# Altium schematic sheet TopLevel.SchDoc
size A
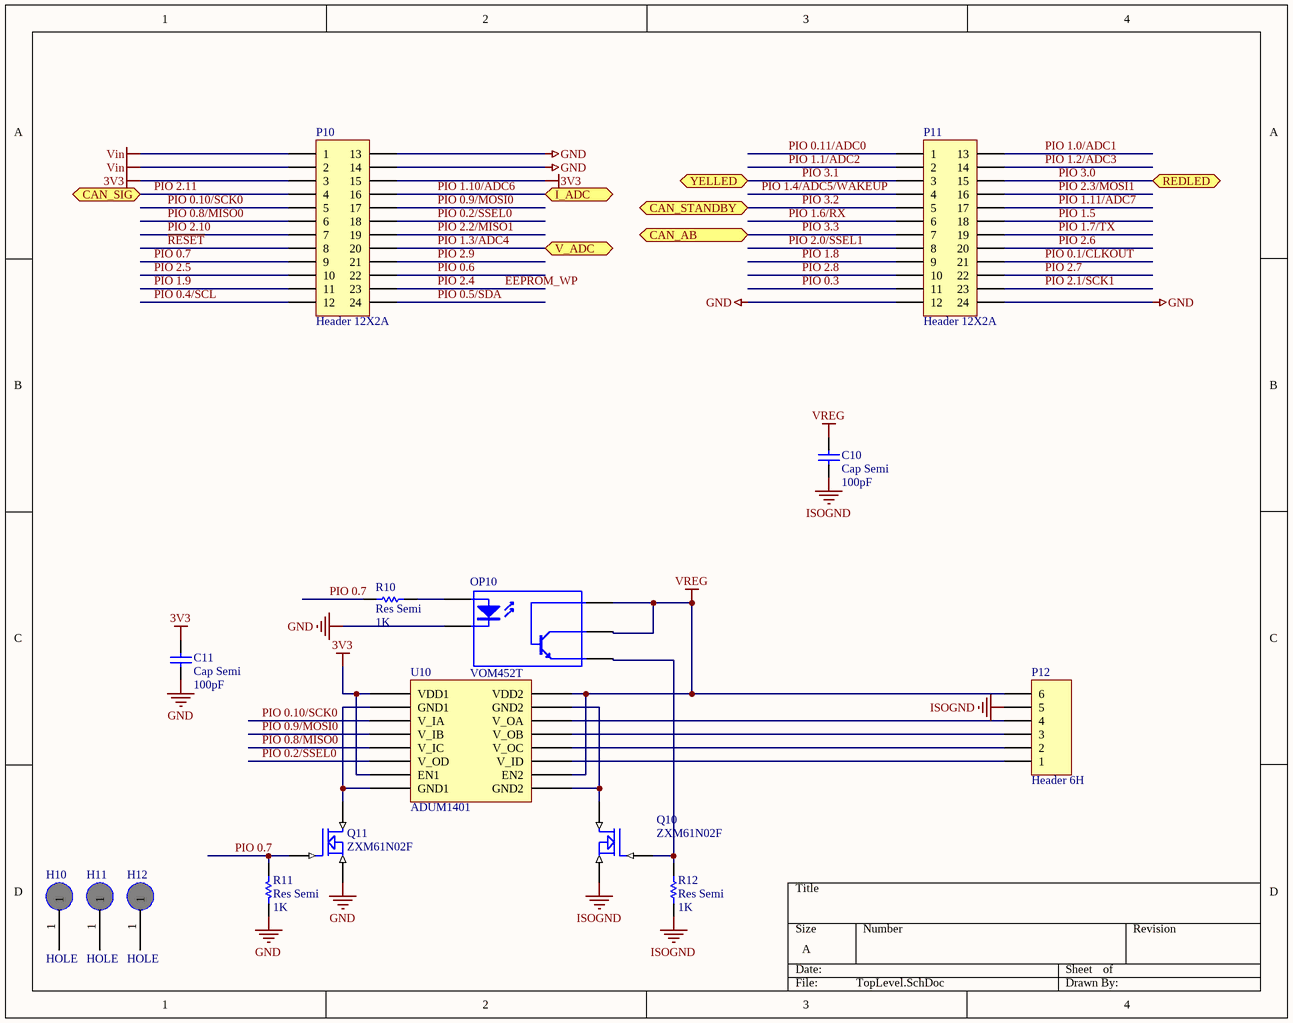
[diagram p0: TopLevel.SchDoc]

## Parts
C10  Cap Semi  value 100pF  [1608[0603]]
C11  Cap Semi  value 100pF  [1608[0603]]
H10  HOLE  [M2.5]
H11  HOLE  [M2.5]
H12  HOLE  [M2.5]
OP10  VOM452T  [VOM452T]
P10  Header 12X2A  [HDR2X12_CEN]
P11  Header 12X2A  [HDR2X12_CEN]
P12  Header 6H  [HDR1X6H]
Q10  ZXM61N02F  [SOT23-3]
Q11  ZXM61N02F  [SOT23-3]
R10  Res Semi  value 1K  [0603]
R11  Res Semi  value 1K  [0603]
R12  Res Semi  value 1K  [0603]
U10  ADUM1401  [SOIC_16_wide]

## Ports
CAN_AB, CAN_SIG, CAN_STANDBY, I_ADC, REDLED (bidir), V_ADC, YELLED (bidir)

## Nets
3V3: C11.2 P10.3 P10.15 U10.1(VDD1) U10.7(EN1)
GND: C11.1 OP10.3(K) P10.13 P10.14 P11.12 P11.24 Q11.2(S) R11.1
ISOGND: C10.1 P12.5 Q10.2(S) R12.1
Vin: P10.1 P10.2
VREG: C10.2 OP10.5(C) OP10.6(C) P12.6 U10.10(EN2) U10.16(VDD2)
EEPROM_WP: P10.23  [also labelled PIO 2.4]
PIO 0.1/CLKOUT: P11.21
PIO 0.2/SSEL0: P10.18 U10.6(V_OD)
PIO 0.3: P11.11
PIO 0.4/SCL: P10.12
PIO 0.5/SDA: P10.24
PIO 0.6: P10.22
PIO 0.7: P10.9 Q11.1(G) R10.2 R11.2
PIO 0.8/MISO0: P10.6 U10.5(V_IC)
PIO 0.9/MOSI0: P10.17 U10.4(V_IB)
PIO 0.10/SCK0: P10.5 U10.3(V_IA)
PIO 0.11/ADC0: P11.1
PIO 1.0/ADC1: P11.13
PIO 1.1/ADC2: P11.2
PIO 1.2/ADC3: P11.14
PIO 1.3/ADC4: P10.20 ; port V_ADC
PIO 1.4/ADC5/WAKEUP: P11.4
PIO 1.5: P11.18
PIO 1.6/RX: P11.6
PIO 1.7/TX: P11.19
PIO 1.8: P11.9
PIO 1.9: P10.11
PIO 1.10/ADC6: P10.16 ; port I_ADC
PIO 1.11/ADC7: P11.17
PIO 2.0/SSEL1: P11.8
PIO 2.1/SCK1: P11.23
PIO 2.2/MISO1: P10.19
PIO 2.3/MOSI1: P11.16
PIO 2.5: P10.10
PIO 2.6: P11.20
PIO 2.7: P11.22
PIO 2.8: P11.10
PIO 2.9: P10.21
PIO 2.10: P10.7
PIO 2.11: P10.4 ; port CAN_SIG
PIO 3.0: P11.15 ; port REDLED
PIO 3.1: P11.3 ; port YELLED
PIO 3.2: P11.5 ; port CAN_STANDBY
PIO 3.3: P11.7 ; port CAN_AB
~{RESET}: P10.8
NetOP10_1: OP10.1(A) R10.1
NetOP10_4: OP10.4(E) Q10.1(G) R12.2
NetP12_1: P12.1 U10.11(V_ID)
NetP12_2: P12.2 U10.12(V_OC)
NetP12_3: P12.3 U10.13(V_OB)
NetP12_4: P12.4 U10.14(V_OA)
NetQ10_3: Q10.3(D) U10.9(GND2) U10.15(GND2)
NetQ11_3: Q11.3(D) U10.2(GND1) U10.8(GND1)

Not connected (* = marked no-connect by the designer): H10 1; H11 1; H12 1

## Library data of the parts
C10 C11 = Cap Semi: Capacitor (Semiconductor SIM Model)
H10-H12 = HOLE: Needed?: NO - Footprint
P10 P11 = Header 12X2A: Header, 12-Pin, Dual row
P12 = Header 6H: Header, 6-Pin, Right Angle
Q10 Q11 = ZXM61N02F: 1.7A, 20V N-Channel Enhancement mode FET; Order#: 9525270
R10-R12 = Res Semi: Semiconductor Resistor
